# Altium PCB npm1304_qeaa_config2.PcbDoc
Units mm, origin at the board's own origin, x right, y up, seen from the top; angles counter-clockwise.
Board outline 16.75 x 14 mm, 4 copper layers (Top Layer, Mid-Layer 1, Mid-Layer 2, Bottom Layer), stack 1.592 mm thick; 14 components, 23 nets, 59 pads, 50 vias.
Unrouted connection lines stored in the file: 20.
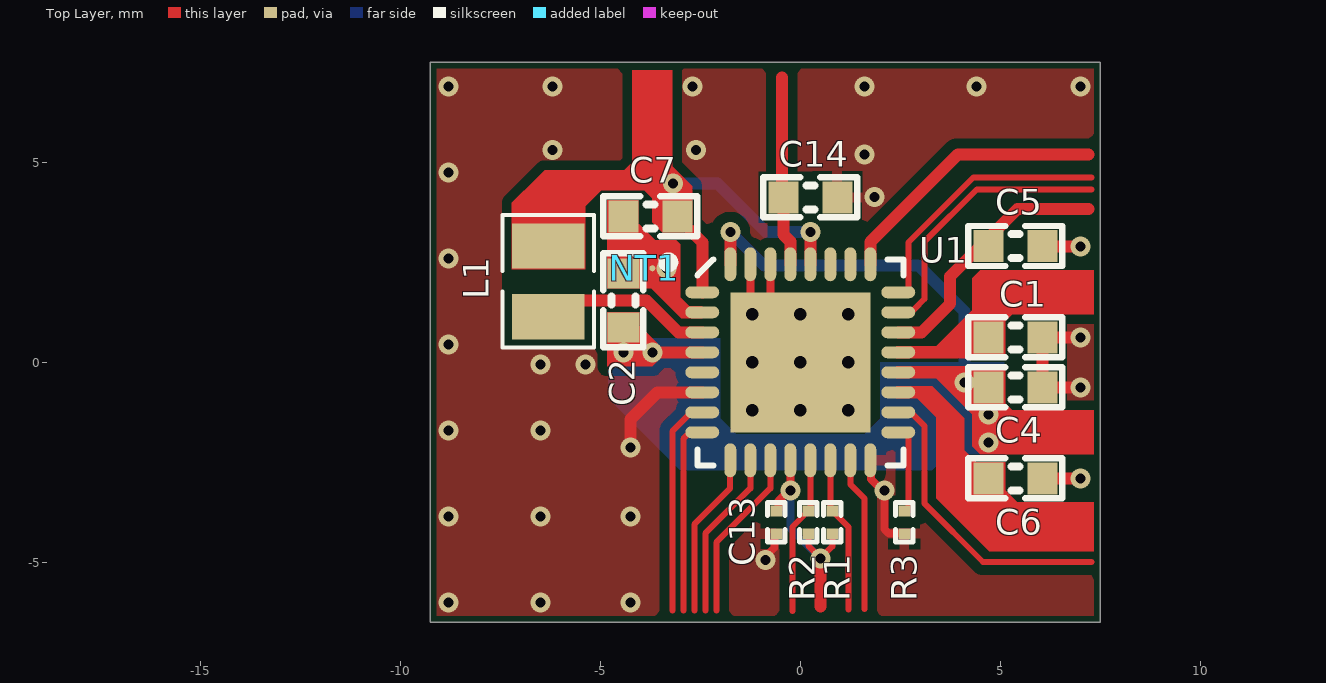
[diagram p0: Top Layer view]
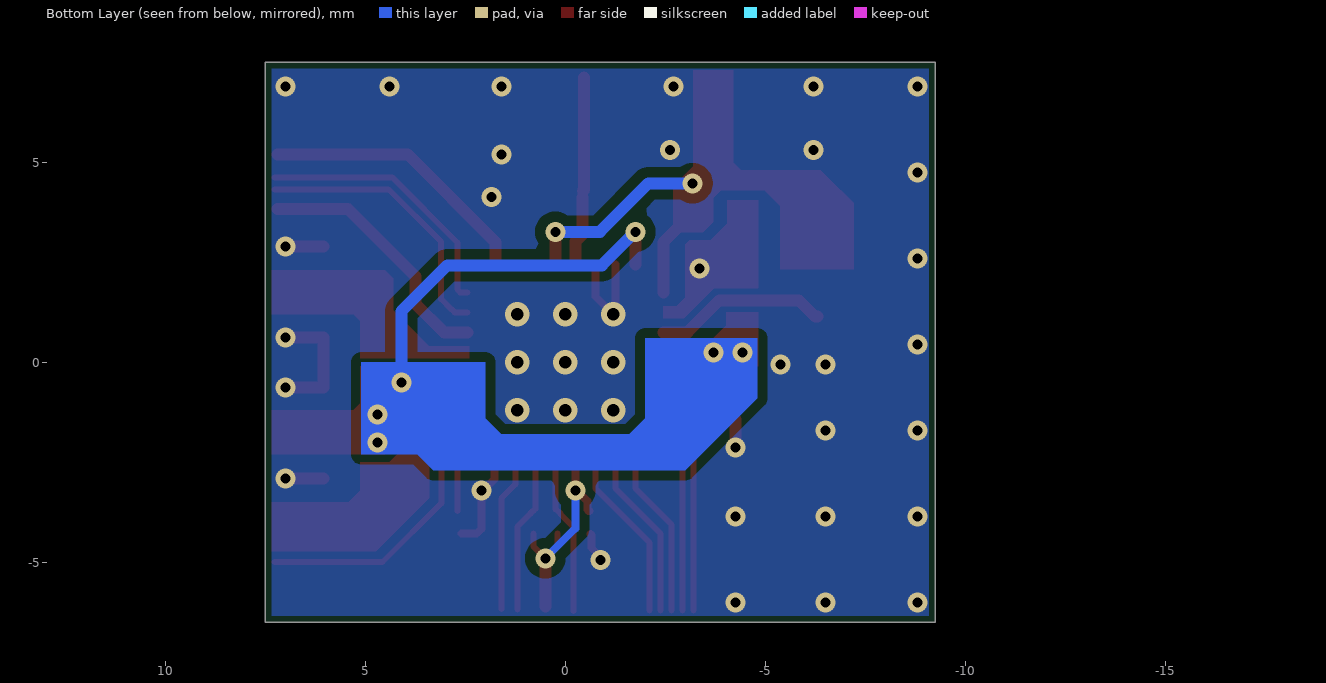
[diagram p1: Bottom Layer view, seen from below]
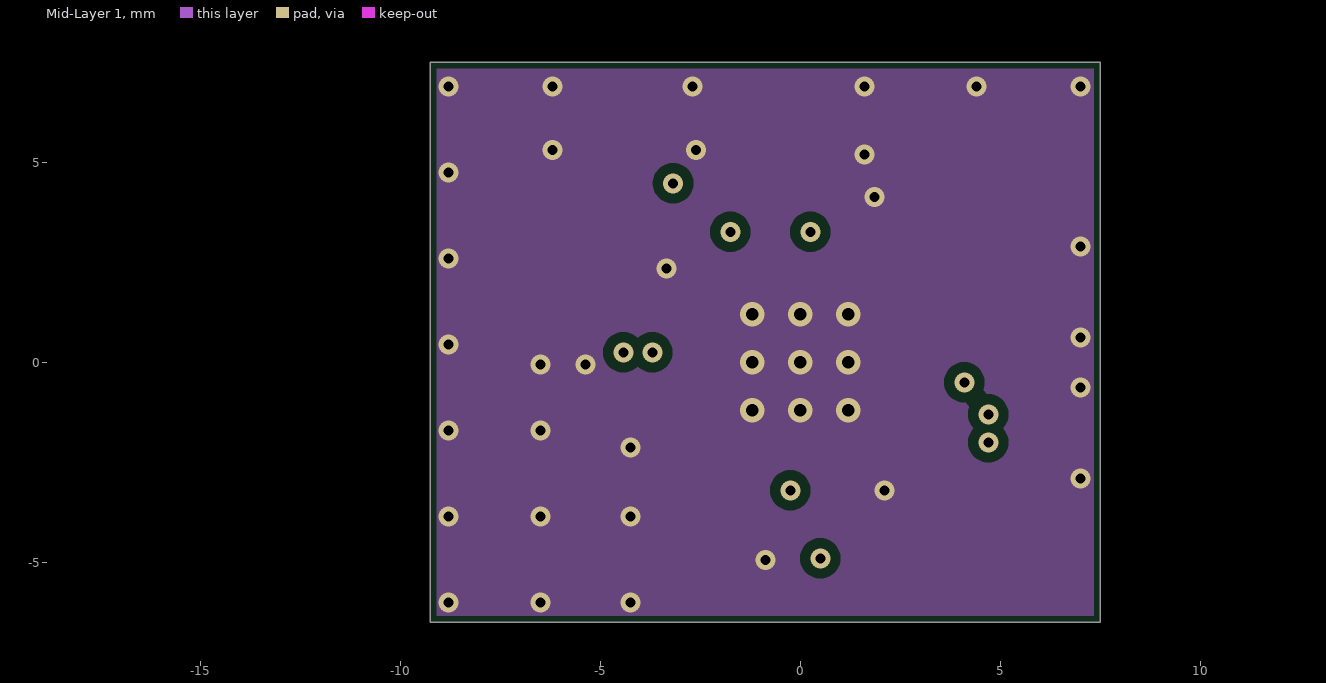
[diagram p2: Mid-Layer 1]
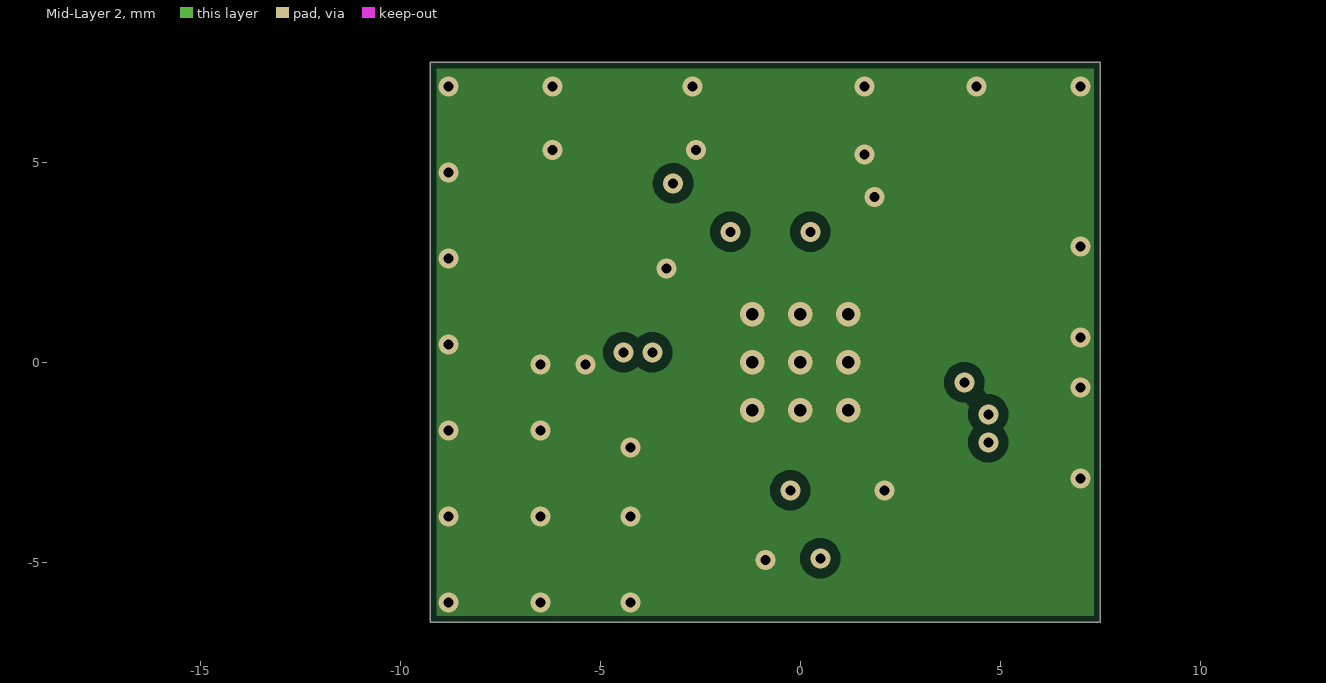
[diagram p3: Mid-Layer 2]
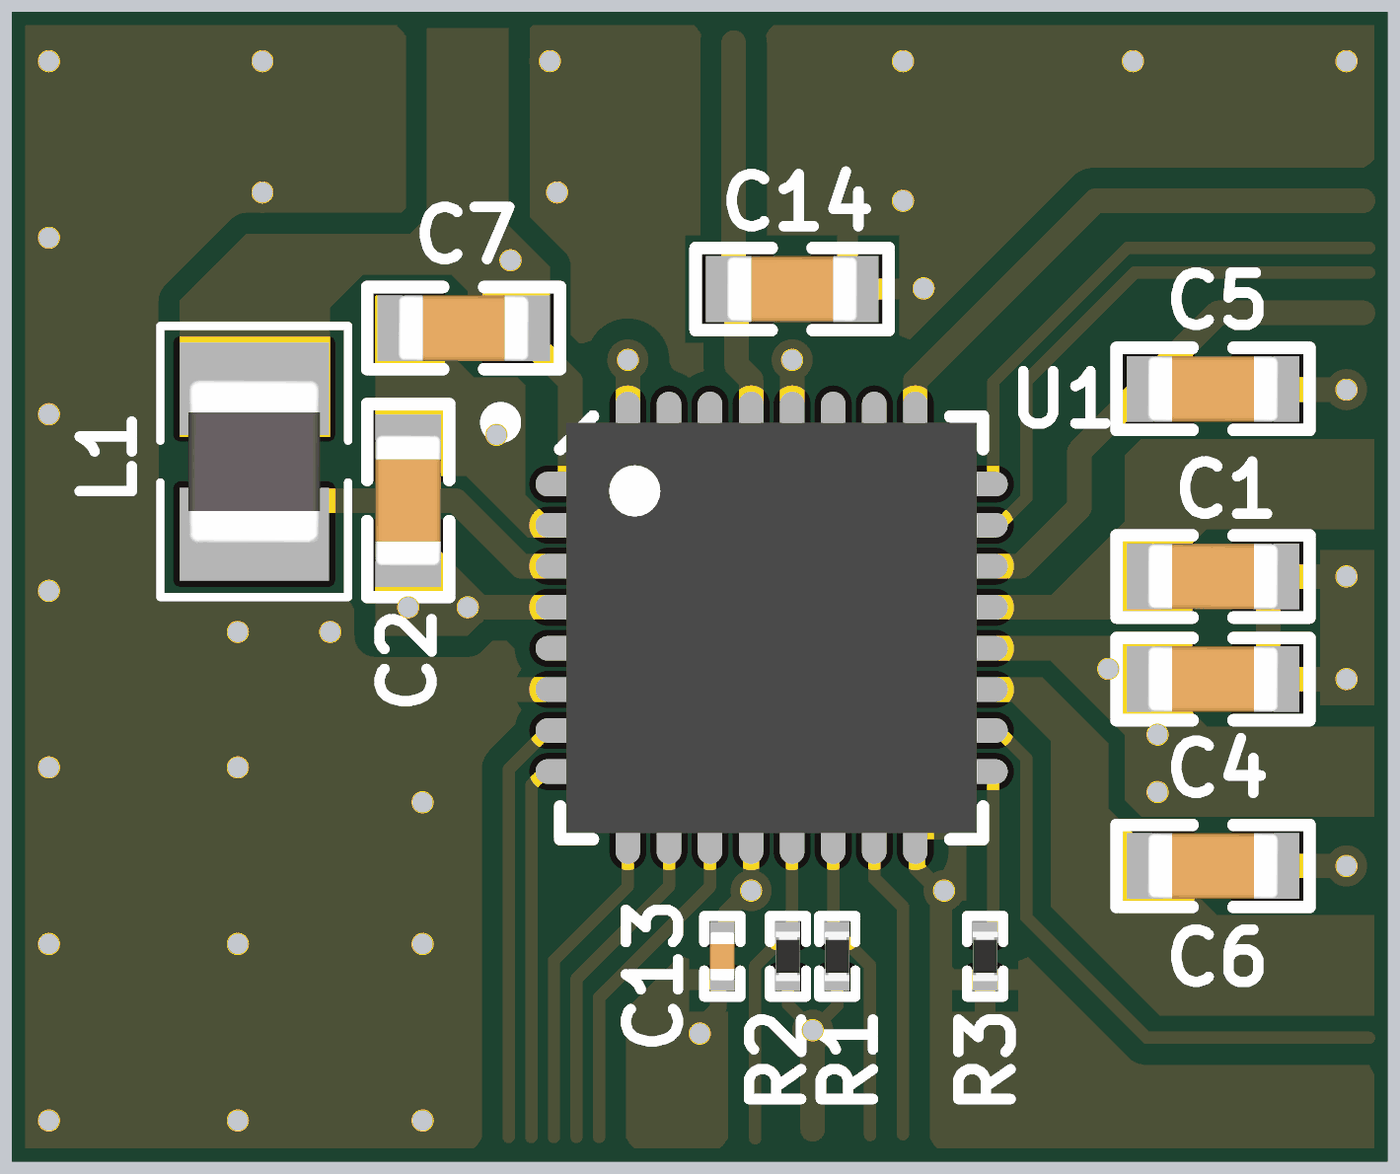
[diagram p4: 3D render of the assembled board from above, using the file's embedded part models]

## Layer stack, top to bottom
Top Solder: solder mask 0.0102, Solder Resist, Dk 3.5
Top Layer: signal copper 0.0356
Dielectric1: prepreg 0.075, FR-4, Dk 4.8
Mid-Layer 1: signal copper 0.0356
Dielectric2: core 1.3, FR-4, Dk 4.8
Mid-Layer 2: signal copper 0.0356
Dielectric 2: prepreg 0.075, FR-4, Dk 4.8
Bottom Layer: signal copper 0.0356
Bottom Solder: solder mask 0.0102, Solder Resist, Dk 3.5

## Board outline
-9.25,7.5 -9.25,-6.5 7.5,-6.5 7.5,7.5

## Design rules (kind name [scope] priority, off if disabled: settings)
BoardOutlineClearance [All] p1: gap=0.15 ignorepadtopadclearanceinfootprint=FALSE
Clearance Polygon_Clearance [(InNamedPolygon('Top_Layer-GND')) or (InNamedPolygon('Bottom_Layer-GND')) or (InNamedPolygon('Mid_Layer_1-GND')) or (InNamedPolygon('Mid_Layer_2-GND'))] p1: gap=0.254 ignorepadtopadclearanceinfootprint=FALSE except(0: Arc-Hole Track-Hole SMDPad-Hole THPad-Hole Via-Hole Fill-Hole Poly-Hole Region-Hole Text-Hole)
Clearance [All] p2: gap=0.125 ignorepadtopadclearanceinfootprint=FALSE
ComponentClearance [All] p1 off: gap=0.254 collisioncheckmode=3 verticalgap=0.254 showdistances=FALSE
DiffPairsRouting [All] p1: maxlimit=0.15 minlimit=0.127 mostfreqgap=0.15 toplayer_mingap=0.15 toplayer_minwidth=0.15 toplayer_maxwidth=0.15 toplayer_prefwidth=0.15 bottomlayer_mingap=0.15 bottomlayer_minwidth=0.15 bottomlayer_maxwidth=0.15 bottomlayer_prefwidth=0.15 impedanceprofiledriven=TRUE impedanceprofileid={DBD80B30-E3CF-4860-A6C7-45E32F93C55D} impedanceprofilevalue=90.000000 maxuncoupledlength=12.7
FabricationTestPointUsage TestPointUsage [All] p1: valid=0 allowmultiple=FALSE
FabricationTestpoint Testpoint [All] p1: side=3 testpointundercomponent=TRUE minsize=1.016 maxsize=2.54 preferedsize=1.524 minholesize=0 maxholesize=1.016 preferedholesize=0.813 testpointgrid=0.025 allowsidetop=TRUE allowsidebottom=TRUE usegrid=TRUE gridtolerance=0
Height [All] p1 off: minheight=0 maxheight=25.4 prefheight=12.7
HoleSize [All] p1: absolutevalues=TRUE maxlimit=5 minlimit=0.1 maxpercent=80.000 minpercent=20.000
MinimumAnnularRing [All] p1 off: minimumring=0.75
PolygonConnect PolygonConnect_GND [InNet('GND')] p1: thpad.connectstyle=Relief thpad.reliefconductorwidth=0.254 thpad.reliefentries=4 thpad.polygonreliefangle="90 Angle" thpad.airgapwidth=0.254 smdpad.connectstyle=Relief smdpad.reliefconductorwidth=0.254 smdpad.reliefentries=4 smdpad.polygonreliefangle="90 Angle" smdpad.airgapwidth=0.254 via.connectstyle=Direct via.reliefconductorwidth=0.254 via.reliefentries=4 via.polygonreliefangle="90 Angle" via.airgapwidth=0.254
PolygonConnect [All] p2: connectstyle=Direct reliefconductorwidth=0.254 reliefentries=4 polygonreliefangle="90 Angle" airgapwidth=0.254
RoutingVias [All] p1: holewidth=0.305 width=0.61 viastyle="Through Hole" minholewidth=0.305 minwidth=0.61 maxholewidth=0.711 maxwidth=1.27 useviatemplates=TRUE viatemplateguid#1={6F225C6A-EE86-4657-A426-C9A0349870D4} viatemplatename#1=v50h25m0mx0
ShortCircuit ShortCircuit_PVSS [InNet('PVSS1') vs InNet('GND')] p1: allowed=TRUE
ShortCircuit [All] p2: allowed=FALSE
SilkToSolderMaskClearance SilkscreenOverComponentPads [IsPad] p1: minsilkscreentomaskgap=0.254 clearancetoexposedcopper=TRUE
SolderMaskExpansion SolderMaskExpansion_Vias [IsVia] p1: expansion=0.102 istentingtop=TRUE
SolderMaskExpansion [All] p2: expansion=0.076 istentingtop=FALSE
SupplyNets "Schematic Supply Nets_7" [InNet('VSYS')] p1: voltage=0.000
SupplyNets "Schematic Supply Nets_6" [InNet('PVSS1')] p2: voltage=0.000
SupplyNets "Schematic Supply Nets_5" [InNet('VBUSOUT')] p3: voltage=0.000
SupplyNets "Schematic Supply Nets_4" [InNet('VBAT')] p4: voltage=0.000
SupplyNets "Schematic Supply Nets_3" [InNet('GND')] p5: voltage=0.000
SupplyNets "Schematic Supply Nets_2" [InNet('VDDIO')] p6: voltage=0.000
SupplyNets "Schematic Supply Nets_1" [InNet('VBUSIN')] p7: voltage=0.000
SupplyNets "Schematic Supply Nets" [InNet('VOUT1')] p8: voltage=0.000
UnRoutedNet [All] p1: checkbadconnections=TRUE
Width [All] p1: maxlimit=2 minlimit=0.12 preferedwidth=0.3
21 further rules are at their usual default settings.

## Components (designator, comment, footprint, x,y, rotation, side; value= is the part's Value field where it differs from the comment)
C1 "1.0µF" CAPC1608X06L 5.375,0.625 r180 top
C2 "10µF" CAPC1608X06L -4.425,1.55 r270 top
C4 "10µF" CAPC1608X06L 5.375,-0.625 r180 top
C5 "1.0µF" CAPC1608X06L 5.375,2.91 r180 top
C6 "2.2µF" CAPC1608X06L 5.375,-2.9 r180 top
C7 "10µF" CAPC1608X06L -3.75,3.65 r0 top
C13 "100nF" CAPC0603X03L_C -0.6,-4 r270 top
C14 "1.0µF" CAPC1608X06L 0.25,4.125 r180 top
L1 "2.2µH" INDC2016X10N -6.3,2.025 r270 top
NT1 "Net tie" "2 PIN STARPOINT" -3.9,2.35 r0 top net-tie
R1 "10k" RESC0603X03L_C 0.8,-4 r270 top
R2 "10k" RESC0603X03L_C 0.2,-4 r270 top
R3 "47k" RESC0603X03L_C 2.6,-4 r270 top
U1 "nPM1304-QEAA" Nordic_QFN50P500X500X90-33N 0,0 r0 top locked

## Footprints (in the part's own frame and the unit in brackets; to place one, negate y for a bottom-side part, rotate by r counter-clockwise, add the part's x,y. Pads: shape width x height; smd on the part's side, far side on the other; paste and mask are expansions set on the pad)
"2 PIN STARPOINT" [mil]
  round 6 smd paste-196.85 mask-196.85: 1(8,0) 2(-8,0)
  Top Layer region: -8,-3 8,-3 8,3 -8,3
CAPC0603X03L_C [mm] "Chip Capacitor, 2-Leads, Body 0.6x0.3mm, IPC High Density"
  rect 0.27x0.3 smd mask+0.05: 1(-0.285,0) 2(0.285,0)
  silkscreen extent -0.49,-0.22 0.49,0.22, body extent -0.3,-0.15 0.3,0.15, height 0.3
CAPC1608X06L [mm] "Chip Capacitor, 2-Leads, Body 1.6x0.8mm, IPC High Density"
  rect 0.75x0.8 smd: 1(-0.675,0) 2(0.675,0)
  silkscreen extent -1.17,-0.5 1.17,0.5, body extent -0.8,-0.4 0.8,0.4, height 0.8
INDC2016X10N [mm] "Chip Inductor, 2-Leads, Body 2.00x1.60mm, IPC Medium Density"
  rect 1.13x1.82 smd: 1(-0.885,0) 2(0.885,0)
  silkscreen extent -1.65,-1.14 1.65,1.14, body extent -1,-0.8 1,0.8, height 1
Nordic_QFN50P500X500X90-33N [mm] "QFN32 5x5x0.85mm, 0.5mm pitch - Medium Density"
  oval 0.85x0.3 smd mask+0.076: 1(-2.45,1.75) 2(-2.45,1.25) 3(-2.45,0.75) 4(-2.45,0.25) 5(-2.45,-0.25) 6(-2.45,-0.75) 7(-2.45,-1.25) 8(-2.45,-1.75) 17(2.45,-1.75) 18(2.45,-1.25) 19(2.45,-0.75) 20(2.45,-0.25) 21(2.45,0.25) 22(2.45,0.75) 23(2.45,1.25) 24(2.45,1.75)
  oval 0.3x0.85 smd mask+0.076: 9(-1.75,-2.45) 10(-1.25,-2.45) 11(-0.75,-2.45) 12(-0.25,-2.45) 13(0.25,-2.45) 14(0.75,-2.45) 15(1.25,-2.45) 16(1.75,-2.45) 25(1.75,2.45) 26(1.25,2.45) 27(0.75,2.45) 28(0.25,2.45) 29(-0.25,2.45) 30(-0.75,2.45) 31(-1.25,2.45) 32(-1.75,2.45)
  rect 3.5x3.5 smd: 33(0,0)
  silkscreen extent -3.42,-2.57 2.57,2.62, body extent -2.5,-2.5 2.5,2.5, height 0.9
RESC0603X03L_C [mm] "Chip Resistor, 2-Leads, Body 0.6x0.3mm, IPC High Density"
  rect 0.27x0.3 smd: 1(-0.285,0) 2(0.285,0)
  silkscreen extent -0.49,-0.22 0.49,0.22, body extent -0.3,-0.15 0.3,0.15, height 0.23

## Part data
C1: library part C0603-1µ0-25V-X5R, "Capacitor, X5R, ±10%, 25V", Manufacturer=N.A., Part number NEMS=100200687
C2 C4 C7: library part C0603-10µ-10V-X5R, "Capacitor, Ceramic, X5R, ±20%, 10V", Manufacturer=N.A., Part number NEMS=100200481, Part number Norautron=262085341
C5 C14: library part C0603-1µ0-10V-X5R, "Capacitor, Ceramic, 1.0µF 10V X5R 0603,±10%", Manufacturer=N.A., Part number NEMS=100200528
C6: library part C0603-2µ2-25V-X5R-GRM188R61E225KA12D, "Capacitor, Ceramic, X5R, ±10%, 25V", Manufacturer=Murata, Manufacturer Part Number=GRM188R61E225KA12D, Part number IPS=N.A., Part number NEMS=100200454, Supplier Part Number 1=490-10731-1-ND
C13: library part C0201-100n-25V-X5R, "Capacitor, Ceramic, X5R, ±10%, 25V", Manufacturer=Murata, Manufacturer Part Number=GRM033R61E104KE14J, Part number IPS=N.A., Part number NEMS=100200459, Supplier Part Number 1=490-14571-1-ND
L1: library part L0806-2µ2-2500mA-73mOhm-CIGT201610EH2R2MNE, "Inductor, Irms=2.5A, Isat=2.9A, ±20%, DCR=73mΩ", Manufacturer="Samsung Electro-Mechanics America", Manufacturer Part Number=CIGT201610EH2R2MNE, Part number IPS=N.A., Part number NEMS=100300400, Part number Norautron=26521789, Supplier Part Number 1=1276-6901-1-ND
NT1: library part "2 pin starpoint", "Starpoint", Manufacturer=N.A., Part number NEMS=100500603
R1 R2: library part R0201-10k, "Resistor, ±1%, 0.05W", Manufacturer=N.A., Part number IPS=00000001255, Part number NEMS=100100065, Part number Norautron=26107101
R3: library part R0201-47k, "Resistor, ±1%, 0.05W", Manufacturer=N.A., Part number IPS=00000001423, Part number NEMS=100100076
U1: "Li-Ion/Li-Polymer USB-C battery charger with high efficiency buck regulators, LDOs or load switches, LED drivers, TWI and VBUSOUT", Manufacturer="Nordic Semiconductor", Part number IPS=N.A., Part number NEMS=102000396

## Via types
v1: diameter 0.5, hole 0.25, Top Layer to Bottom Layer, tented both sides, 41 vias
v2: diameter 0.61, hole 0.305, Top Layer to Bottom Layer, tented both sides, 9 vias

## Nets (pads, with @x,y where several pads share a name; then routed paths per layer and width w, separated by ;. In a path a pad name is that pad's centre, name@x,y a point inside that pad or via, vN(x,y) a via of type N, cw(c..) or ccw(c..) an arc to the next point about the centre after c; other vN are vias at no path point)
CC1: U1.23 | length 6.9
  Top Layer w0.15: U1.23 2.766,1.25 2.841,1.325 2.846,1.325 3.104,1.583 3.104,3.011 4.418,4.325 7.275,4.325
CC2: U1.24 | length 6.7
  Top Layer w0.15: U1.24 2.631,1.75 2.7,1.819 2.7,2.995 4.33,4.625 7.275,4.625
GND: C1.1 C4.1 C5.1 C6.1 C13.2 C14.1 NT1.1 R3.2 U1.6 U1.16 U1.30 U1.31 U1.33 | length 13.3
  Top Layer w0.15: NT1.1 v1(-3.35,2.35)
  Top Layer w0.2: U1.31 -1.25,1.25 v2(-1.2,1.2) -0.75,1.65 U1.30 ; v1(-0.875,-4.941) -0.875,-4.859 -0.65,-4.634 -0.65,-4.315 C13.2@-0.627,-4.292 ; U1.16 1.769,-2.469 1.769,-2.923 2.046,-3.2 v1(2.1,-3.2) 2.1,-4.168 2.217,-4.285 R3.2
  Top Layer w0.3: v1(-4.25,-2.125) -4.25,-1.43 -3.57,-0.75 U1.6 ; C6.1 v1@6.9,-2.9 ; C4.1 C1.1 v1@6.8,0.625 ; C5.1@6.05,2.9 v1@6.8,2.9 ; C4.1@6.125,-0.625 v1@6.8,-0.625
  other v1: -8.8,-6 -6.5,-6 -4.25,-6 -8.8,-3.85 -6.5,-3.85 -4.25,-3.85 7,-2.9 -8.8,-1.7 -6.5,-1.7 7,-0.625 -6.5,-0.05 -5.375,-0.05 -8.8,0.45 7,0.625 -8.8,2.6 7,2.9 1.85,4.133 -8.8,4.75 1.6,5.2 -6.2,5.302 -2.612,5.302 -8.8,6.9 -6.2,6.9 -2.7,6.9 1.6,6.9 4.4,6.9 7,6.9
  other v2: -1.2,-1.2 0,-1.2 1.2,-1.2 -1.2,0 0,0 1.2,0 0,1.2 1.2,1.2
GPIO0: U1.7 | length 5.4
  Top Layer w0.15: -3.2,-6.2 -3.2,-1.725 -2.725,-1.25 U1.7
GPIO1: U1.8 | length 4.8
  Top Layer w0.15: -2.925,-6.2 -2.925,-1.913 -2.762,-1.75 U1.8
GPIO2: U1.9 | length 4.1
  Top Layer w0.15: -2.65,-6.2 -2.65,-4.05 -1.753,-3.153 -1.753,-2.453 U1.9
GPIO3: U1.10 | length 4.2
  Top Layer w0.15: -2.375,-6.2 -2.375,-4.275 -1.25,-3.15 U1.10
GPIO4: U1.11 | length 4.9
  Top Layer w0.15: -2.1,-6.2 -2.1,-4.5 -0.75,-3.15 U1.11 -0.75,-3.05
LED0: U1.25 | length 6.9
  Top Layer w0.3: U1.25 1.75,3.008 3.942,5.2 7.2,5.2
LSOUT1: C14.2 U1.29 | length 4.9
  Top Layer w0.3: -0.463,5.113 -0.463,4.85 ; -0.463,7.125 -0.463,4.85 ; C14.2@-0.438,4.288 -0.463,4.313 -0.463,4.85 ; C14.2 -0.425,3.195 -0.25,3.02 U1.29
NTC: U1.18 | length 7.5
  Top Layer w0.15: U1.18 2.761,-1.25 3.1,-1.589 3.1,-3.525 4.568,-4.993 7.275,-4.993
PVSS1: C2.1 C7.1 NT1.2 U1.2
SCL: R1.1 U1.14 | length 3.9
  Top Layer w0.15: U1.14 0.75,-3.665 R1.1 0.815,-3.715 0.875,-3.775 0.875,-3.79 1.2,-4.115 1.2,-6.178
SDA: R2.1 U1.13 | length 4
  Top Layer w0.15: -0.2,-6.216 -0.2,-4.117 0.125,-3.792 0.125,-3.775 0.22,-3.68 0.25,-3.68 U1.13
SHPHLD: U1.15 | length 3.9
  Top Layer w0.15: U1.15 1.25,-3.05 1.6,-3.4 1.6,-6.166
SW1: L1.2 U1.3 | length 4.4
  Top Layer w0.3: L1.2 -6.25,1.14 -5.84,1.55 -3.85,1.55 -3.05,0.75 U1.3
VBAT: C6.2 U1.19
VBUSIN: C1.2 U1.21
VBUSOUT: C5.2 U1.22 | length 6.4
  Top Layer w0.3: U1.22 3.033,0.75 3.748,1.465 3.748,2.148 4.613,3.013 5.434,3.834 7.2,3.834
VDDIO: C13.1 R1.2 R2.2 U1.12 | length 6.2
  Top Layer w0.15: R2.2 0.2,-4.586 v1@0.45,-4.836 ; v1@0.5,-4.786 v1(0.5,-4.9) 0.8,-4.6 R1.2
  Top Layer w0.2: C13.1 -0.585,-3.715 -0.55,-3.68 -0.55,-3.467 -0.283,-3.2 v1(-0.25,-3.2) -0.25,-3 U1.12
  Top Layer w0.3: 0.5,-6.106 v1(0.5,-4.9)
  Bottom Layer w0.2: v1(-0.25,-3.2) -0.25,-4.15 v1(0.5,-4.9)
VOUT1: C7.2 L1.1 U1.1 U1.28 | length 8.1
  Top Layer w0.3: L1.1@-5.955,2.91 L1.1@-5.54,3.325 ; C7.2@-3.3,3.9 -3.212,3.812 C7.2@-3.212,3.787 ; C7.2@-3.154,3.9 -3.179,3.875 -3.3,3.875 C7.2 -3.075,3.625 -2.45,3 U1.1 ; U1.28 0.25,2.862 v1(0.25,3.263)
  Bottom Layer w0.3: v1(-3.179,4.475) -2.075,4.475 -0.863,3.263 v1(0.25,3.263)
VSET1: R3.1 U1.17 | length 2.2
  Top Layer w0.15: U1.17 2.631,-1.75 2.7,-1.819 R3.1@2.7,-3.715
VSYS: C2.2 C4.2 U1.4 U1.20 U1.32 | length 10.4
  Top Layer w0.3: v1@-3.596,0.25 U1.4 ; U1.32 v1(-1.75,3.263)
  Bottom Layer w0.3: v1(-1.75,3.263) -0.912,2.425 2.947,2.425 4.1,1.272 v1(4.1,-0.5)
  other v1: 4.7,-2 4.7,-1.3 -4.425,0.25 -3.7,0.25
pads on no net: U1.5 U1.26 U1.27

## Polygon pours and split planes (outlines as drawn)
GND on Mid-Layer 1 "Mid_Layer_1-GND" (solid, remove dead copper, pour order 24): -9.25,-6.5 7.5,-6.5 7.5,7.5 -9.25,7.5
GND on Mid-Layer 2 "Mid_Layer_2-GND" (solid, remove dead copper, pour order 25): -9.25,-6.5 7.5,-6.5 7.5,7.5 -9.25,7.5
GND on Top Layer "Top_Layer-GND" (solid, remove dead copper, pour order 21): -9.25,-6.5 7.5,-6.5 7.5,7.5 -9.25,7.5
GND on Bottom Layer "Bottom_Layer-GND" (solid, remove dead copper, pour order 26): -9.25,-6.5 7.5,-6.5 7.5,7.5 -9.25,7.5

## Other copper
Top Layer:
  pour cut-out: -4.8,2.106 -4.8,2.894 -3.138,2.894 -3.138,2.106
  region net VOUT1: -6.593,4.6 -6.393,4.8 -4.4,4.8 -4.2,5 -4.2,7.3 -3.2,7.3 -3.2,4.9 -2.7,4.4 -2.7,3.25 -3.45,3.25 -3.704,3.504 -3.704,4.096 -3.7,4.1 -3.9,4.3 -6.593,4.3
  region net VBAT: 2.4,-0.9 2.925,-0.9 3.4,-1.375 3.4,-3.4 4.725,-4.725 7.338,-4.725 7.338,-3.5 5.425,-3.5 5.125,-3.2 5.125,-2.5 4.4,-2.5 4.1,-2.2 4.1,-1.4 3.3,-0.6 2.4,-0.6
  region net VSYS: 5.125,-0.1 5.125,-1.025 5.3,-1.2 7.338,-1.2 7.338,-2.3 4.5,-2.3 4.3,-2.1 4.3,-1.3 3.4,-0.4 2.4,-0.4 2.4,-0.1
  region net VBUSIN: 5.125,0.1 5.125,1.025 5.3,1.2 7.338,1.2 7.338,2.3 4.5,2.3 4.3,2.1 4.3,1.3 3.4,0.4 2.4,0.4 2.4,0.1
  pour cut-out: -1.85,1.85 1.85,1.85 1.85,-1.85 -1.85,-1.85
  region net VOUT1: -4.925,4.35 -5.375,3.9 -5.375,2.325 -7.21,2.325 -7.21,3.983 -6.593,4.6 -4.925,4.6
  region net PVSS1: -4.825,4.05 -4.05,4.05 -4.05,3.475 -3.625,3.05 -3.1,3.05 -3,2.95 -3,1.625 -2.775,1.4 -2.45,1.4 -2.45,1.1 -2.975,1.1 -3.725,1.85 -4.825,1.85
  pour cut-out: -7.464,2.325 -7.464,1.7 -5.375,1.7 -5.375,2.325
  region net VSYS: -3.5,0.4 -4.025,0.925 -4.025,1.25 -4.825,1.25 -4.825,-0.1 -3.7,-0.1 -3.5,0.1
  pour cut-out: -17.9,1.7 -17.9,-3.2
  pour cut-out: 7.375,0.45 7.375,-0.41
Mid-Layer 1:
  pour cut-out: 11.025,5.525 12.025,5.525
Bottom Layer:
  region net VSYS: -4.8,0.6 -4.8,-0.9 -3,-2.7 3.3,-2.7 3.7,-2.3 5.1,-2.3 5.1,0 2,0 2,-1.4 1.6,-1.8 -1.6,-1.8 -2,-1.4 -2,0.6

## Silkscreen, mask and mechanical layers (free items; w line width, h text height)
Board Outline:
  the board outline again, w0.2

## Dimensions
7.5,-6.5 to 7.5,7.5 on Dimension
-9.25,-6.5 to 7.5,-6.5 on Dimension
